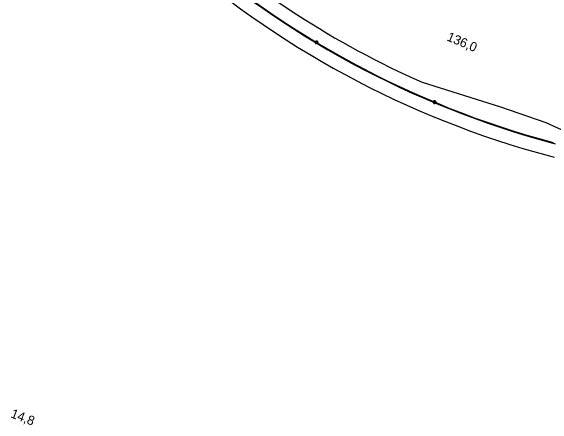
# Model space of a CAD drawing. Extents: x -670810 to -649614, y -1131928 to -1115069.
# Drawn here: x -665597 to -661499, y -1130367 to -1127234 of the extents above; entities that cross this region are included whole.
import ezdxf

# ---------------------------------------------------------------- set-up
doc = ezdxf.new("R2010")
doc.units = 0
for name, color, linetype in [('hranice_VRT_ZUR_Vysocina', 7, 'Continuous'), ('Situace - Osa koleje 2D', 7, 'Continuous'), ('Staničení - hlavní staničení + kolečka 1k', 7, 'Continuous')]:
    doc.layers.add(name, color=color, linetype=linetype)

# ---------------------------------------------------------------- blocks, each defined once
blk = doc.blocks.new('Sit10Kruh_112')
at = {"layer": 'Staničení - hlavní staničení + kolečka 1k'}
blk.add_lwpolyline([(10, 0), (9.98026, 0.6279), (9.92114, 1.25334), (9.82288, 1.87382), (9.68584, 2.4869), (9.51056, 3.09016), (9.29776, 3.68124), (9.04828, 4.2578), (8.76306, 4.81754), (8.44328, 5.35826), (8.09016, 5.87786), (7.70514, 6.37424), (7.28968, 6.84548), (6.84548, 7.28968), (6.37424, 7.70514), (5.87786, 8.09016), (5.35826, 8.44328), (4.81754, 8.76306), (4.2578, 9.04828), (3.68124, 9.29776), (3.09016, 9.51056), (2.4869, 9.68584), (1.87382, 9.82288), (1.25334, 9.92114), (0.6279, 9.98026), (0, 10), (-0.6279, 9.98026), (-1.25334, 9.92114), (-1.87382, 9.82288), (-2.4869, 9.68584), (-3.09016, 9.51056), (-3.68124, 9.29776), (-4.2578, 9.04828), (-4.81754, 8.76306), (-5.35826, 8.44328), (-5.87786, 8.09016), (-6.37424, 7.70514), (-6.84548, 7.28968), (-7.28968, 6.84548), (-7.70514, 6.37424), (-8.09016, 5.87786), (-8.44328, 5.35826), (-8.76306, 4.81754), (-9.04828, 4.2578), (-9.29776, 3.68124), (-9.51056, 3.09016), (-9.68584, 2.4869), (-9.82288, 1.87382), (-9.92114, 1.25334), (-9.98026, 0.6279), (-10, 0), (-9.98026, -0.6279), (-9.92114, -1.25334), (-9.82288, -1.87382), (-9.68584, -2.4869), (-9.51056, -3.09016), (-9.29776, -3.68124), (-9.04828, -4.2578), (-8.76306, -4.81754), (-8.44328, -5.35826), (-8.09016, -5.87786), (-7.70514, -6.37424), (-7.28968, -6.84548), (-6.84548, -7.28968), (-6.37424, -7.70514), (-5.87786, -8.09016), (-5.35826, -8.44328), (-4.81754, -8.76306), (-4.2578, -9.04828), (-3.68124, -9.29776), (-3.09016, -9.51056), (-2.4869, -9.68584), (-1.87382, -9.82288), (-1.25334, -9.92114), (-0.6279, -9.98026), (0, -10), (0.6279, -9.98026), (1.25334, -9.92114), (1.87382, -9.82288), (2.4869, -9.68584), (3.09016, -9.51056), (3.68124, -9.29776), (4.2578, -9.04828), (4.81754, -8.76306), (5.35826, -8.44328), (5.87786, -8.09016), (6.37424, -7.70514), (6.84548, -7.28968), (7.28968, -6.84548), (7.70514, -6.37424), (8.09016, -5.87786), (8.44328, -5.35826), (8.76306, -4.81754), (9.04828, -4.2578), (9.29776, -3.68124), (9.51056, -3.09016), (9.68584, -2.4869), (9.82288, -1.87382), (9.92114, -1.25334)], close=True, dxfattribs=at)
blk.add_circle((0, 0), 10, dxfattribs=at)
blk = doc.blocks.new('Sit10Kruh_113')
at = {"layer": 'Staničení - hlavní staničení + kolečka 1k'}
blk.add_lwpolyline([(10, 0), (9.98026, 0.6279), (9.92114, 1.25334), (9.82288, 1.87382), (9.68584, 2.4869), (9.51056, 3.09016), (9.29776, 3.68124), (9.04828, 4.2578), (8.76306, 4.81754), (8.44328, 5.35826), (8.09016, 5.87786), (7.70514, 6.37424), (7.28968, 6.84548), (6.84548, 7.28968), (6.37424, 7.70514), (5.87786, 8.09016), (5.35826, 8.44328), (4.81754, 8.76306), (4.2578, 9.04828), (3.68124, 9.29776), (3.09016, 9.51056), (2.4869, 9.68584), (1.87382, 9.82288), (1.25334, 9.92114), (0.6279, 9.98026), (0, 10), (-0.6279, 9.98026), (-1.25334, 9.92114), (-1.87382, 9.82288), (-2.4869, 9.68584), (-3.09016, 9.51056), (-3.68124, 9.29776), (-4.2578, 9.04828), (-4.81754, 8.76306), (-5.35826, 8.44328), (-5.87786, 8.09016), (-6.37424, 7.70514), (-6.84548, 7.28968), (-7.28968, 6.84548), (-7.70514, 6.37424), (-8.09016, 5.87786), (-8.44328, 5.35826), (-8.76306, 4.81754), (-9.04828, 4.2578), (-9.29776, 3.68124), (-9.51056, 3.09016), (-9.68584, 2.4869), (-9.82288, 1.87382), (-9.92114, 1.25334), (-9.98026, 0.6279), (-10, 0), (-9.98026, -0.6279), (-9.92114, -1.25334), (-9.82288, -1.87382), (-9.68584, -2.4869), (-9.51056, -3.09016), (-9.29776, -3.68124), (-9.04828, -4.2578), (-8.76306, -4.81754), (-8.44328, -5.35826), (-8.09016, -5.87786), (-7.70514, -6.37424), (-7.28968, -6.84548), (-6.84548, -7.28968), (-6.37424, -7.70514), (-5.87786, -8.09016), (-5.35826, -8.44328), (-4.81754, -8.76306), (-4.2578, -9.04828), (-3.68124, -9.29776), (-3.09016, -9.51056), (-2.4869, -9.68584), (-1.87382, -9.82288), (-1.25334, -9.92114), (-0.6279, -9.98026), (0, -10), (0.6279, -9.98026), (1.25334, -9.92114), (1.87382, -9.82288), (2.4869, -9.68584), (3.09016, -9.51056), (3.68124, -9.29776), (4.2578, -9.04828), (4.81754, -8.76306), (5.35826, -8.44328), (5.87786, -8.09016), (6.37424, -7.70514), (6.84548, -7.28968), (7.28968, -6.84548), (7.70514, -6.37424), (8.09016, -5.87786), (8.44328, -5.35826), (8.76306, -4.81754), (9.04828, -4.2578), (9.29776, -3.68124), (9.51056, -3.09016), (9.68584, -2.4869), (9.82288, -1.87382), (9.92114, -1.25334)], close=True, dxfattribs=at)
blk.add_circle((0, 0), 10, dxfattribs=at)

msp = doc.modelspace()

# ---------------------------------------------------------------- linework, layer by layer
at = {"layer": 'hranice_VRT_ZUR_Vysocina'}
for points in [[(-662489.9, -1127774.2), (-661897.9, -1127961.1), (-661554.5, -1128077.7), (-661377.3, -1128159.3)], [(-661525.9, -1128331.8), (-661525.8, -1128331.8), (-661508.9, -1128336.3), (-661492, -1128340.8)]]:
    msp.add_lwpolyline(points, dxfattribs=at)
for centre, radius, start, end in [((-659686.8, -1121469.2), 6900, 228.12762, 246.0305), ((-659686.8, -1121469.3), 7104.7, 228.12694, 254.9977)]:
    msp.add_arc(centre, radius, start, end, dxfattribs=at)
at = {"layer": 'Situace - Osa koleje 2D'}
msp.add_lwpolyline([(-661500, -1128235.2), (-661483.3, -1128239.7)], dxfattribs=at)
for radius, start, end in [(7004.7, 228.12698, 254.99766), (7000, 228.12757, 254.99706)]:
    msp.add_arc((-659686.8, -1121469.3), radius, start, end, dxfattribs=at)

# ---------------------------------------------------------------- block references
at = {"layer": 'Staničení - hlavní staničení + kolečka 1k'}
for name, p, rotation in [('Sit10Kruh_112', (-663287, -1127472.5), -30.951693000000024), ('Sit10Kruh_113', (-662395.6, -1127923.9), -22.766581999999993)]:
    msp.add_blockref(name, p, dxfattribs=dict(at, rotation=rotation))

# ---------------------------------------------------------------- texts
for s, rotation, p in [('136,0', 337.2334, (-662308.1, -1127456.3)), ('14,8', 339.0299, (-665603.6, -1130306.6)), ('14,8', 339.0299, (-665603.6, -1130306.6))]:
    msp.add_text(s, height=70, rotation=rotation, dxfattribs=at).set_placement(p)

doc.saveas('drawing.dxf')
